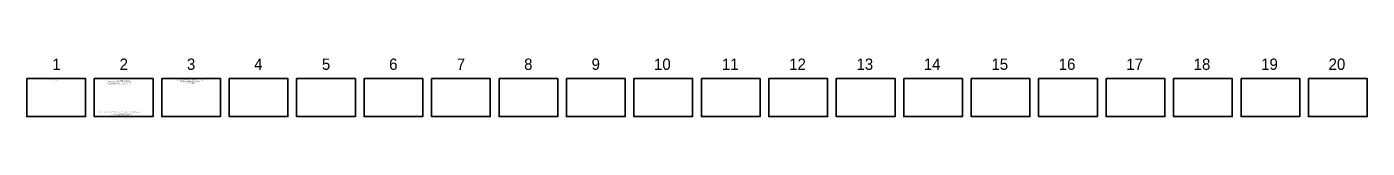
# Model space of a CAD drawing. Extents: x 10133 to 81668, y 7924 to 11018.
import ezdxf

# ---------------------------------------------------------------- set-up
doc = ezdxf.new("R2010")
doc.units = 0
doc.layers.add('DisROW Survey', color=7, linetype='Continuous')
doc.layers.add('Safety', color=7, linetype='Continuous')

msp = doc.modelspace()

# ---------------------------------------------------------------- linework, layer by layer
at = {"layer": 'DisROW Survey'}
for points in [[(10133, 9944), (13268, 9944), (13268, 7924), (10133, 7924)], [(13733, 9944), (16868, 9944), (16868, 7924), (13733, 7924)], [(17333, 9944), (20468, 9944), (20468, 7924), (17333, 7924)], [(20933, 9944), (24068, 9944), (24068, 7924), (20933, 7924)], [(24533, 9944), (27668, 9944), (27668, 7924), (24533, 7924)], [(28133, 9944), (31268, 9944), (31268, 7924), (28133, 7924)], [(31733, 9944), (34868, 9944), (34868, 7924), (31733, 7924)], [(35333, 9944), (38468, 9944), (38468, 7924), (35333, 7924)], [(38933, 9944), (42068, 9944), (42068, 7924), (38933, 7924)], [(42533, 9944), (45668, 9944), (45668, 7924), (42533, 7924)], [(46133, 9944), (49268, 9944), (49268, 7924), (46133, 7924)], [(49733, 9944), (52868, 9944), (52868, 7924), (49733, 7924)], [(53333, 9944), (56468, 9944), (56468, 7924), (53333, 7924)], [(56933, 9944), (60068, 9944), (60068, 7924), (56933, 7924)], [(60533, 9944), (63668, 9944), (63668, 7924), (60533, 7924)], [(64133, 9944), (67268, 9944), (67268, 7924), (64133, 7924)], [(67733, 9944), (70868, 9944), (70868, 7924), (67733, 7924)], [(71333, 9944), (74468, 9944), (74468, 7924), (71333, 7924)], [(74933, 9944), (78068, 9944), (78068, 7924), (74933, 7924)], [(78533, 9944), (81668, 9944), (81668, 7924), (78533, 7924)]]:
    msp.add_lwpolyline(points, close=True, dxfattribs=at)

# ---------------------------------------------------------------- texts
at = {"layer": 'Safety'}
for s, height, p in [('1', 600, (11497, 10409)), ('2', 600, (15086, 10409)), ('3', 600, (18678, 10409)), ('4', 600, (22268, 10409)), ('5', 600, (25881, 10409)), ('6', 600, (29470, 10409)), ('7', 600, (33080, 10409)), ('8', 600, (36673, 10409)), ('9', 600, (40273, 10409)), ('10', 600, (43606, 10409)), ('11', 600, (47230, 10409)), ('12', 600, (50820, 10409)), ('13', 600, (54411, 10409)), ('14', 600, (58001, 10409)), ('15', 600, (61614, 10409)), ('16', 600, (65204, 10409)), ('17', 600, (68814, 10409)), ('18', 600, (72406, 10409)), ('19', 600, (76007, 10409)), ('20', 600, (79606, 10409)), ('Survey Information', 28, (11511, 9855)), ('This map is a guide to the vicinity of the primary project control points. ', 30, (14422, 9772)), ('control as needed for construction or other surveying applications.', 30, (14422, 9622)), ('Primary control is for use with RTK base stations and for RTN validation. ', 30, (14422, 9722)), ('Future surveys will use primary project control to establish temporary ', 30, (14422, 9672)), ('CONTROL POINT VICINITY MAP', 30, (14967, 9842)), (' HORIZ. DATUM: NAD83(2011) for EPOCH 2010.00 (IaRTN 2019 Adjustment)', 30, (18082, 9809)), ('HORIZONTAL AND VERTICAL PROJECT CONTROL COORDINATE LISTING', 30, (18110, 9865)), ('       Ia. Regional Coordinate System Zone 06 (U.S. Survey Foot)', 30, (18215, 9769)), ('VERT. DATUM: NAVD88', 30, (18651, 9717)), (' Geoid Model: 2018u2 ', 30, (18666, 9677)), (' HORIZ. DATUM: NAD83(2011) for EPOCH 2010.00 (IaRTN 2019 Adjustment) - Iowa RCS Zone 06 (U.S. Survey Foot)', 30, (13979, 8152)), ('Coordinate listing from next sheet will be used with IaRTN for monument ', 30, (14449, 8037)), ('VERT. DATUM: NAVD88 - Geoid Model: 2018u2', 30, (14762, 8094)), ('recovery. No other reference ties are given. ', 30, (14788, 7997))]:
    msp.add_text(s, height=height, dxfattribs=at).set_placement(p)

doc.saveas('drawing.dxf')
